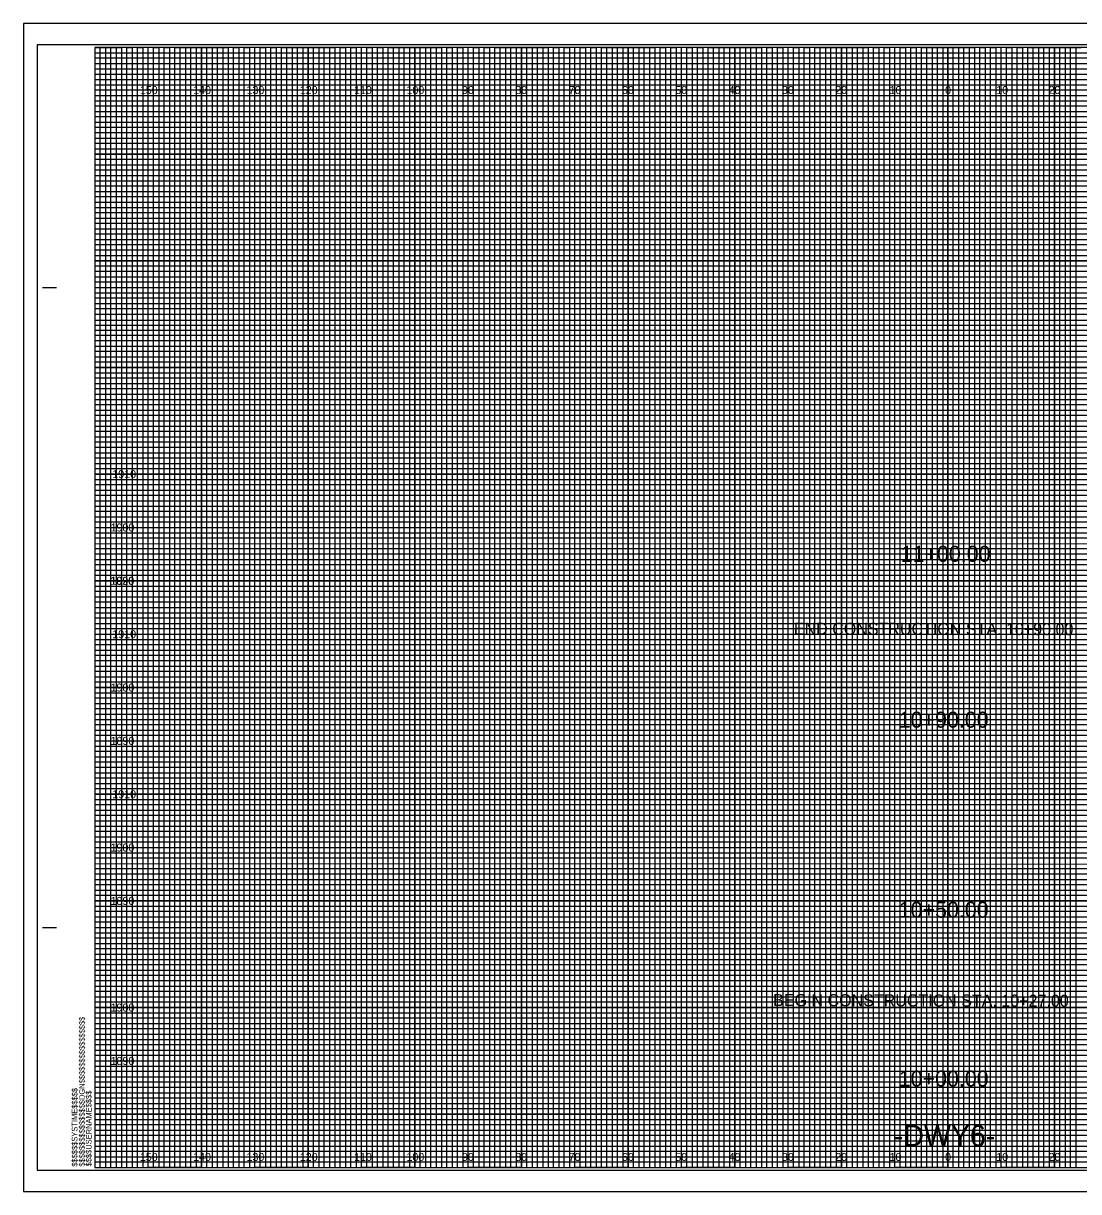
# Model space of a CAD drawing. Extents: x -13 to 323, y -4 to 214.
# Drawn here: x -13.4 to 184.5, y -4.5 to 214.5 of the extents above; entities that cross this region are included whole.
import ezdxf

# ---------------------------------------------------------------- set-up
doc = ezdxf.new("R2010")
doc.units = 0
for name, color, linetype in [('Prop XS Alignment Label', 7, 'Continuous'), ('Prop XS Elevation Labels', 7, 'Continuous'), ('Prop XS Offset Labels', 7, 'Continuous'), ('Prop XS SE Text', 7, 'Continuous'), ('Prop XS Station Labels', 7, 'Continuous'), ('Sheet Cross Section CELL', 7, 'Continuous'), ('Sheet Cross Section Grid Major CELL', 7, 'Continuous'), ('Sheet Cross Section Grid Middle CELL', 7, 'Continuous'), ('Sheet Cross Section Grid Minor 1 CELL', 7, 'Continuous'), ('Sheet Cross Section Grid Minor 2 CELL', 7, 'Continuous'), ('Sheet Cutting Line CELL', 7, 'Continuous'), ('Sheet DOT Grid CELL', 7, 'Continuous'), ('Sheet Plot Border Inside CELL', 7, 'Continuous'), ('Sheet Plot Border Outside CELL', 7, 'Continuous')]:
    doc.layers.add(name, color=color, linetype=linetype)

msp = doc.modelspace()

# ---------------------------------------------------------------- linework, layer by layer
at = {"layer": 'Sheet Cross Section CELL'}
for p, q in [((-9.8, 165), (-7.3, 165)), ((-9.7, 165), (-7.2, 165)), ((-9.8, 45), (-7.3, 45)), ((-9.7, 45), (-7.2, 45))]:
    msp.add_line(p, q, dxfattribs=at)
msp.add_lwpolyline([(320, 210), (0, 210), (0, 0), (320, 0)], close=True, dxfattribs=at)
at = {"layer": 'Sheet Cross Section Grid Major CELL'}
for p, q in [((10, 210), (0, 210)), ((10, 0), (10, 210)), ((30, 210), (20, 210)), ((20, 210), (20, 0)), ((30, 0), (30, 210)), ((50, 210), (40, 210)), ((40, 210), (40, 0)), ((50, 0), (50, 210)), ((70, 210), (60, 210)), ((60, 210), (60, 0)), ((70, 0), (70, 210)), ((90, 210), (80, 210)), ((80, 210), (80, 0)), ((90, 0), (90, 210)), ((110, 210), (100, 210)), ((100, 210), (100, 0)), ((110, 0), (110, 210)), ((130, 210), (120, 210)), ((120, 210), (120, 0)), ((130, 0), (130, 210)), ((150, 210), (140, 210)), ((140, 210), (140, 0)), ((150, 0), (150, 210)), ((170, 210), (160, 210)), ((160, 210), (160, 0)), ((170, 0), (170, 210)), ((190, 210), (180, 210)), ((180, 210), (180, 0)), ((20, 0), (10, 0)), ((40, 0), (30, 0)), ((60, 0), (50, 0)), ((80, 0), (70, 0)), ((100, 0), (90, 0)), ((120, 0), (110, 0)), ((140, 0), (130, 0)), ((160, 0), (150, 0)), ((180, 0), (170, 0))]:
    msp.add_line(p, q, dxfattribs=at)
for points in [[(0, 200), (320, 200), (320, 190), (0, 190)], [(0, 180), (320, 180), (320, 170), (0, 170)], [(0, 160), (320, 160), (320, 150), (0, 150)], [(0, 140), (320, 140), (320, 130), (0, 130)], [(0, 120), (320, 120), (320, 110), (0, 110)], [(0, 100), (320, 100), (320, 90), (0, 90)], [(0, 80), (320, 80), (320, 70), (0, 70)], [(0, 60), (320, 60), (320, 50), (0, 50)], [(0, 40), (320, 40), (320, 30), (0, 30)], [(0, 20), (320, 20), (320, 10), (0, 10)]]:
    msp.add_lwpolyline(points, dxfattribs=at)
at = {"layer": 'Sheet Cross Section Grid Middle CELL'}
for points in [[(0, 210), (5, 210), (5, 0), (15, 0), (15, 210), (25, 210), (25, 0), (35, 0), (35, 210), (45, 210), (45, 0), (55, 0), (55, 210), (65, 210), (65, 0), (75, 0), (75, 210), (85, 210), (85, 0), (95, 0), (95, 210), (105, 210), (105, 0), (115, 0), (115, 210), (125, 210), (125, 0), (135, 0), (135, 210), (145, 210), (145, 0), (155, 0), (155, 210), (165, 210), (165, 0), (175, 0), (175, 210), (185, 210)], [(0, 205), (275, 205)], [(0, 185), (320, 185), (320, 195), (0, 195)], [(0, 165), (320, 165), (320, 175), (0, 175)], [(0, 145), (320, 145), (320, 155), (0, 155)], [(0, 125), (320, 125), (320, 135), (0, 135)], [(0, 105), (320, 105), (320, 115), (0, 115)], [(0, 85), (320, 85), (320, 95), (0, 95)], [(0, 65), (320, 65), (320, 75), (0, 75)], [(0, 45), (320, 45), (320, 55), (0, 55)], [(0, 25), (320, 25), (320, 35), (0, 35)], [(0, 5), (320, 5), (320, 15), (0, 15)]]:
    msp.add_lwpolyline(points, dxfattribs=at)
at = {"layer": 'Sheet Cross Section Grid Minor 1 CELL'}
for p, q in [((0, 209), (260, 209)), ((260, 207.98), (0, 207.98)), ((0, 207.98), (0, 207)), ((0, 207), (260, 207)), ((260, 205.89), (0, 205.89)), ((0, 205.89), (0, 204)), ((0, 204), (320, 204))]:
    msp.add_line(p, q, dxfattribs=at)
for points in [[(0, 203), (270, 203), (320, 203), (320, 202), (0, 202)], [(0, 201), (320, 201), (320, 199), (0, 199)], [(0, 198), (320, 198), (320, 197), (0, 196.98)], [(0, 196), (320, 196), (320, 194), (0, 194)], [(0, 193), (320, 193), (320, 192), (0, 192)], [(0, 191), (320, 191), (320, 189), (0, 189)], [(0, 188), (320, 188), (320, 187), (0, 187)], [(0, 186), (320, 186), (320, 184), (0, 184)], [(0, 183), (320, 183), (320, 182), (0, 182)], [(0, 181), (320, 181), (320, 179), (0, 179)], [(0, 178), (320, 178), (320, 177), (0, 177)], [(0, 176), (320, 176), (320, 173.95), (320, 173), (320, 172), (0, 172)], [(0, 174), (320, 174), (320, 173), (0, 173)], [(0, 171), (320, 171), (320, 169), (0, 169.03)], [(0, 169.03), (320, 169), (320, 168), (0, 168)], [(0, 167), (320, 167), (320, 166), (0, 166)], [(0, 164), (320, 164), (320, 163), (0, 163)], [(0, 162), (320, 162), (320, 161), (0, 161)], [(-0.07, 158.89), (320, 158.89), (320, 157.88), (-0.07, 157.88)], [(0, 157), (320, 157), (320, 156), (0, 156)], [(0, 154), (320, 154), (320, 153), (0, 153)], [(0, 152), (320, 152), (320, 151), (0, 151)], [(0, 149), (320, 149), (320, 148), (0, 148)], [(0, 147), (320, 147), (320, 146), (0, 146)], [(0, 144), (320, 144), (320, 143), (0, 143)], [(0, 142), (320, 142), (320, 141), (0, 141)], [(0, 139), (320, 139), (319.99, 137.98), (0, 138)], [(0, 137), (320, 137), (320, 136), (0, 136)], [(0, 134), (320, 134), (320, 133), (0, 133)], [(0, 132), (320, 132), (320, 131), (0, 131)], [(0, 129), (320, 129), (320, 128), (0, 128)], [(0, 127), (320, 127), (320, 126), (0, 126)], [(0, 124), (320, 124), (320, 123), (0, 123)], [(0, 122), (320, 122), (320, 121), (0, 121)], [(0, 119), (320, 119), (320, 118), (0, 118)], [(0, 116.99), (320.07, 116.91), (320, 116), (0, 116)], [(0, 114), (320, 114), (320, 113), (0, 113)], [(0, 112), (320, 112), (320, 111), (0, 111)], [(0, 109), (320, 109), (320, 108), (0, 108)], [(0, 107), (320, 107), (320, 106), (0, 106)], [(0, 104), (320, 104), (320, 103), (0, 103)], [(0, 102), (320, 102), (320, 101), (0, 101)], [(0, 99), (320, 99), (320, 98), (0, 98)], [(0, 97), (320, 97), (320, 96), (0, 96)], [(0, 94), (320, 94), (320, 93), (0, 93)], [(0, 92), (320, 92), (320, 91), (0, 91)], [(0, 89), (320, 89), (320, 88), (0, 88)], [(0, 87), (320, 87), (320, 86), (0, 86)], [(0, 84), (320, 84), (320, 83), (0, 83)], [(0, 82), (320, 82), (320, 81), (0, 81)], [(0, 79), (320, 79), (319.99, 77.98), (0, 78)], [(0, 77), (320, 77), (320, 76), (0, 76)], [(0, 74), (320, 74), (320, 73), (0, 73)], [(0, 72), (320, 72), (320, 71), (0, 71)], [(0, 69), (320, 69), (320, 68), (0, 68)], [(0, 67), (320, 67), (320, 66), (0, 66)], [(0, 64), (320, 64), (320, 63), (0, 63)], [(0, 62), (320, 62), (320, 61), (0, 61)], [(0, 59), (320, 59), (320, 58), (0, 58)], [(0, 56.99), (320.07, 56.91), (320, 56), (0, 56)], [(0, 54), (320, 54), (320, 53), (0, 53)], [(0, 52), (320, 52), (320, 51), (0, 51)], [(0, 49), (320, 49), (320, 48), (0, 48)], [(0, 47), (320, 47), (320, 46), (0, 46)], [(0, 44), (320, 44), (320, 43), (0, 43)], [(0, 42), (320, 42), (320, 41), (0, 41)], [(0, 39), (320, 39), (320, 38), (0, 38)], [(0, 37), (320, 37), (320, 36), (0, 36)], [(0, 34), (320, 34), (320, 33), (0, 33)], [(0, 32), (320, 32), (320, 31), (0, 31)], [(0, 29), (320, 29), (320, 28), (0, 28)], [(0, 27), (320, 27), (320, 26), (0, 26)], [(0, 24), (320, 24), (320, 23), (0, 23)], [(0, 22), (320, 22), (320, 21), (0, 21)], [(0, 19), (320, 19), (320, 18), (0, 18)], [(0, 17), (320, 17), (320, 16), (0, 16)], [(0, 14), (320, 14), (320, 13), (0, 13)], [(0, 12), (320, 12), (320, 11), (0, 11)], [(0, 9), (320, 9), (320, 8), (0, 8)], [(0, 7), (320, 7), (320, 6), (0, 6)], [(0, 4), (320, 4), (320, 3), (0, 3)], [(0, 2), (320, 2), (320, 1), (0, 1)]]:
    msp.add_lwpolyline(points, dxfattribs=at)
at = {"layer": 'Sheet Cross Section Grid Minor 2 CELL'}
for points in [[(0, 0), (1, 0), (1, 210), (2, 210), (2, 0)], [(2, 0), (3, 0), (3, 210), (4, 210), (4, 0)], [(5, 0), (6, 0), (6, 210), (7, 210), (7, 0)], [(7, 0), (8, 0), (8, 210), (9, 210), (9, 0)], [(10, 0), (11, 0), (11, 210), (12, 210), (12, 0)], [(12, 0), (13, 0), (13, 210), (14, 210), (14, 0)], [(15, 0), (16, 0), (16, 210), (17, 210), (17, 0)], [(17, 0), (18, 0), (18, 210), (19, 210), (19, 0)], [(20, 0), (21, 0), (21, 210), (22, 210), (22, 0)], [(22, 0), (23, 0), (23, 210), (24, 210), (24, 0)], [(25, 0), (26, 0), (26, 210), (27, 210), (27, 0)], [(27, 0), (28, 0), (28, 210), (29, 210), (29, 0)], [(30, 0), (31, 0), (31, 210), (32, 210), (32, 0)], [(32, 0), (33, 0), (33, 210), (34, 210), (34, 0)], [(35, 0), (36, 0), (36, 210), (37, 210), (37, 0)], [(37, 0), (38, 0), (38, 210), (39, 210), (39, 0)], [(40, 0), (41, 0), (41, 210), (42, 210), (42, 0)], [(42, 0), (43, 0), (43, 210), (44, 210), (44, 0)], [(45, 0), (46, 0), (46, 210), (47, 210), (47, 0)], [(47, 0), (48, 0), (48, 210), (49, 210), (49, 0)], [(50, 0), (51, 0), (51, 210), (52, 210), (52, 0)], [(52, 0), (53, 0), (53, 210), (54, 210), (54, 0)], [(55, 0), (56, 0), (56, 210), (57, 210), (57, 0)], [(57, 0), (58, 0), (58, 210), (59, 210), (59, 0)], [(60, 0), (61, 0), (61, 210), (62, 210), (62, 0)], [(62, 0), (63, 0), (63, 210), (64, 210), (64, 0)], [(65, 0), (66, 0), (66, 210), (67, 210), (67, 0)], [(67, 0), (68, 0), (68, 210), (69, 210), (69, 0)], [(70, 0), (71, 0), (71, 210), (72, 210), (72, 0)], [(72, 0), (73, 0), (73, 210), (74, 210), (74, 0)], [(75, 0), (76, 0), (76, 210), (77, 210), (77, 0)], [(77, 0), (78, 0), (78, 210), (79, 210), (79, 0)], [(80, 0), (81, 0), (81, 210), (82, 210), (82, 0)], [(82, 0), (83, 0), (83, 210), (84, 210), (84, 0)], [(85, 0), (86, 0), (86, 210), (87, 210), (87, 0)], [(87, 0), (88, 0), (88, 210), (89, 210), (89, 0)], [(90, 0), (91, 0), (91, 210), (92, 210), (92, 0)], [(92, 0), (93, 0), (93, 210), (94, 210), (94, 0)], [(95, 0), (96, 0), (96, 210), (97, 210), (97, 0)], [(97, 0), (98, 0), (98, 210), (99, 210), (99, 0)], [(100, 0), (101, 0), (101, 210), (102, 210), (102, 0)], [(102, 0), (103, 0), (103, 210), (104, 210), (104, 0)], [(105, 0), (106, 0), (106, 210), (107, 210), (107, 0)], [(107, 0), (108, 0), (108, 210), (109, 210), (109, 0)], [(110, 0), (111, 0), (111, 210), (112, 210), (112, 0)], [(112, 0), (113, 0), (113, 210), (114, 210), (114, 0)], [(115, 0), (116, 0), (116, 210), (117, 210), (117, 0)], [(117, 0), (118, 0), (118, 210), (119, 210), (119, 0)], [(120, 0), (121, 0), (121, 210), (122, 210), (122, 0)], [(122, 0), (123, 0), (123, 210), (124, 210), (124, 0)], [(125, 0), (126, 0), (126, 210), (127, 210), (127, 0)], [(127, 0), (128, 0), (128, 210), (129, 210), (129, 0)], [(130, 0), (131, 0), (131, 210), (132, 210), (132, 0)], [(132, 0), (133, 0), (133, 210), (134, 210), (134, 0)], [(135, 0), (136, 0), (136, 210), (137, 210), (137, 0)], [(137, 0), (138, 0), (138, 210), (139, 210), (139, 0)], [(140, 0), (141, 0), (141, 210), (142, 210), (142, 0)], [(142, 0), (143, 0), (143, 210), (144, 210), (144, 0)], [(145, 0), (146, 0), (146, 210), (147, 210), (147, 0)], [(147, 0), (148, 0), (148, 210), (149, 210), (149, 0)], [(150, 0), (151, 0), (151, 210), (152, 210), (152, 0)], [(152, 0), (153, 0), (153, 210), (154, 210), (154, 0)], [(155, 0), (156, 0), (156, 210), (157, 210), (157, 0)], [(157, 0), (158, 0), (158, 210), (159, 210), (159, 0)], [(160, 0), (161, 0), (161, 210), (162, 210), (162, 0)], [(162, 0), (163, 0), (163, 210), (164, 210), (164, 0)], [(165, 0), (166, 0), (166, 210), (167, 210), (167, 0)], [(167, 0), (168, 0), (168, 210), (169, 210), (169, 0)], [(170, 0), (171, 0), (171, 210), (172, 210), (172, 0)], [(172, 0), (173, 0), (173, 210), (174, 210), (174, 0)], [(175, 0), (176, 0), (176, 210), (177, 210), (177, 0)], [(177, 0), (178, 0), (178, 210), (179, 210), (179, 0)], [(180, 0), (181, 0), (181, 210), (182, 210), (182, 0)], [(182, 0), (183, 0), (183, 210), (184, 210), (184, 0)]]:
    msp.add_lwpolyline(points, dxfattribs=at)
at = {"layer": 'Sheet Cutting Line CELL'}
for p, q in [((323.3, 214.5), (-13.4, 214.5)), ((-13.4, 214.5), (-13.4, -4.5)), ((-13.4, -4.5), (323.3, -4.5))]:
    msp.add_line(p, q, dxfattribs=at)
at = {"layer": 'Sheet DOT Grid CELL'}
for p, q in [((10, 0), (10, 210)), ((20, 0), (20, 210)), ((30, 0), (30, 210)), ((40, 0), (40, 210)), ((50, 0), (50, 210)), ((60, 0), (60, 210)), ((70, 0), (70, 210)), ((80, 0), (80, 210)), ((90, 0), (90, 210)), ((100, 0), (100, 210)), ((110, 0), (110, 210)), ((120, 0), (120, 210)), ((130, 0), (130, 210)), ((140, 0), (140, 210)), ((150, 0), (150, 210)), ((160, 0), (160, 210)), ((170, 0), (170, 210)), ((180, 0), (180, 210)), ((0, 200), (320, 200)), ((0, 190), (320, 190)), ((0, 180), (320, 180)), ((0, 170), (320, 170)), ((0, 160), (320, 160)), ((0, 150), (320, 150)), ((0, 140), (320, 140)), ((0, 130), (320, 130)), ((0, 120), (320, 120)), ((0, 110), (320, 110)), ((0, 100), (320, 100)), ((0, 90), (320, 90)), ((0, 80), (320, 80)), ((0, 70), (320, 70)), ((0, 60), (320, 60)), ((0, 50), (320, 50)), ((0, 40), (320, 40)), ((0, 30), (320, 30)), ((0, 20), (320, 20)), ((0, 10), (320, 10))]:
    msp.add_line(p, q, dxfattribs=at)
at = {"layer": 'Sheet Plot Border Inside CELL'}
msp.add_lwpolyline([(-10.8, -0.5), (322.4, -0.5), (322.4, 210.5), (-10.8, 210.5)], close=True, dxfattribs=at)
at = {"layer": 'Sheet Plot Border Outside CELL'}
msp.add_lwpolyline([(-13.4, -4.5), (323.3, -4.5), (323.3, 214.5), (-13.4, 214.5)], close=True, dxfattribs=at)

# ---------------------------------------------------------------- texts
at = {"layer": 'Prop XS Alignment Label'}
msp.add_text('-DWY6-', height=4, dxfattribs=at).set_placement((149.85, 4))
at = {"layer": 'Prop XS Elevation Labels'}
for s, p in [('1910', (3.28, 129.25)), ('1900', (2.95, 119.25)), ('1920', (2.9, 109.25)), ('1890', (2.95, 109.25)), ('1910', (3.28, 99.25)), ('1900', (2.95, 89.25)), ('1890', (2.95, 79.25)), ('1910', (3.28, 69.25)), ('1900', (2.95, 59.25)), ('1890', (2.95, 49.25)), ('1900', (2.95, 29.25)), ('1890', (2.95, 19.25))]:
    msp.add_text(s, height=1.5, dxfattribs=at).set_placement(p)
at = {"layer": 'Prop XS Offset Labels'}
for s, p in [('150', (8.44, 201.25)), ('140', (18.44, 201.25)), ('130', (28.44, 201.25)), ('120', (38.44, 201.25)), ('110', (48.62, 201.25)), ('100', (58.44, 201.25)), ('90', (68.86, 201.25)), ('80', (78.86, 201.25)), ('70', (88.86, 201.25)), ('60', (98.86, 201.25)), ('50', (108.86, 201.25)), ('40', (118.86, 201.25)), ('30', (128.86, 201.25)), ('20', (138.86, 201.25)), ('10', (149.04, 201.25)), ('0', (159.45, 201.25)), ('0', (159.45, 201.25)), ('10', (169.04, 201.25)), ('20', (178.86, 201.25)), ('150', (8.44, 1.25)), ('140', (18.44, 1.25)), ('130', (28.44, 1.25)), ('120', (38.44, 1.25)), ('110', (48.62, 1.25)), ('100', (58.44, 1.25)), ('90', (68.86, 1.25)), ('80', (78.86, 1.25)), ('70', (88.86, 1.25)), ('60', (98.86, 1.25)), ('50', (108.86, 1.25)), ('40', (118.86, 1.25)), ('30', (128.86, 1.25)), ('20', (138.86, 1.25)), ('10', (149.04, 1.25)), ('0', (159.45, 1.25)), ('0', (159.45, 1.25)), ('10', (169.04, 1.25)), ('20', (178.86, 1.25))]:
    msp.add_text(s, height=1.5, dxfattribs=at).set_placement(p)
at = {"layer": 'Prop XS SE Text'}
for s, p in [('END CONSTRUCTION STA. 10+90.00', (131.09, 99.92)), ('BEGIN CONSTRUCTION STA. 10+27.00', (127.21, 30.28))]:
    msp.add_text(s, height=2.25, rotation=359.878, dxfattribs=at).set_placement(p)
at = {"layer": 'Prop XS Station Labels'}
for s, p in [('11+00.00', (151.13, 113.56)), ('10+90.00', (150.77, 82.47)), ('10+50.00', (150.77, 46.85)), ('10+00.00', (150.77, 15.2))]:
    msp.add_text(s, height=3, dxfattribs=at).set_placement(p)
at = {"layer": 'Sheet Cross Section CELL'}
for s, p in [('$$$$$$$$$$$$$$$$DGN$$$$$$$$$$$$$$$$', (-1.88, 0.18)), ('$$$$$$SYSTIME$$$$$', (-3.26, 0.18)), ('$$$$USERNAME$$$$', (-0.62, 0.23))]:
    msp.add_text(s, height=1.05, rotation=90, dxfattribs=at).set_placement(p)

doc.saveas('drawing.dxf')
